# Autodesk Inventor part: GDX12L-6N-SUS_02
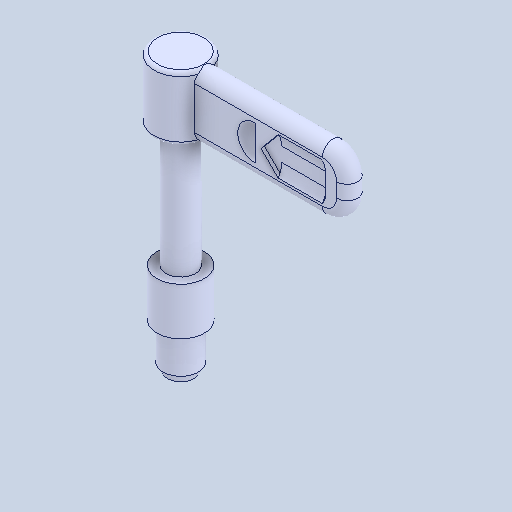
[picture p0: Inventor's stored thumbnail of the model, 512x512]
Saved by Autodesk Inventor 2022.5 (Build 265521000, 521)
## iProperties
Created: 2024-06
Part Number: GDX12L-6N-SUS_02
Material: 一般
Document SubType Name: Modeling
Designer: ImaoCorp
Density: 1 g/cm^3
Appearance: 既定
Author: ImaoCorp
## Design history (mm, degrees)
feature "GDX12L-6N-SUS_02"
node "ソリッド1"
